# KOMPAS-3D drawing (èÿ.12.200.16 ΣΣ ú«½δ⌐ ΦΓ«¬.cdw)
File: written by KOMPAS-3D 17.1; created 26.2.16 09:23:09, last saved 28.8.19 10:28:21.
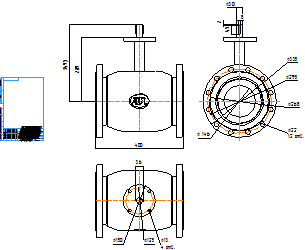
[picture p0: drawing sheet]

Sheet 1: A4, portrait

Title block, sheet 1: name: КШ.12.200.16 Ф/Ф голый шток; mass: 58,3; sheets: 1; sheet format: A4; stored path: C:\Users\kka\KOMPAS_Work\Модели кранов для исследований\DN200\КШ.12.200.16 фф голый шток.cdw

Views: Вид 1, Проекционный вид 2, Проекционный вид 3
Referenced files in C:\Users\kka\KOMPAS_Work\Модели кранов для исследований\DN200\: КШ.12.200.25 фф + Q-800-S.m3d
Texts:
  Klimkovich
  ADL
  Рама для чертежей
  Лит-Масса-Масштаб
  Материал-Предприятие
  Масштаб
  Изм.
  Лист
  № докум.
  Подп.
  Дата
  Лит.
  Разраб.
  Пров.
  Т.контр.
  Листов
  Внимание! Данный продукт является объектом авторского права ООО «Торговый Дом АДЛ».
  Запрещается изменение, копирование, распространение
  (в том числе путем копирования на другие сайты и ресурсы в Интернете)
  или любое иное использование информации и объектов без предварительного
  согласия правообладателя (ООО «Торговый Дом АДЛ»).
  Н.контр.
  Утв.
  ООО "Торговый дом АДЛ"
  Изменение
  Номер документа
  Подпись
  Обозначение документа
  Наименование изделия
  Масса изделия по ГОСТ 2.109-73
  Порядковый номер листа
  Общее количество листов в документе
  Характер работы, выполненной лицом, подписавшим документ
  Наименование или индекс предприятия, выпускающего документ
  Инв. № подл.
  Подп. и дата
  Взам. инв. №
  Инв. № дубл.
  Инвентарный номер подлинника по ГОСТ 2.501-68
  Подпись принявшего подлинник в отдел технической документации
  Инвентарный номер подлинника, взамен которого выпущен данный подлинник
  Инвентарный номер дубликата по ГОСТ 2.502-68
  Подпись принявшего дубликат в отдел технической документации
  Справ. №
  Перв. примен.
  Обозначение документа, взамен или на основании которого выпущен данный документ
  Обозначение документа, в котором впервые записан данный документ
  Подпись лица, копировавшего чертеж
  Обозначение формата листа
  !Рама для чертежа
Dimensions and other numbers on the sheet: 349,5; 289; 400; 146; 335; 295; 268; 22; 12 отв.; 30; 8; 45; 2; 150; 125; 13; 4 отв.; 36; 1:1; 1; 58,3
